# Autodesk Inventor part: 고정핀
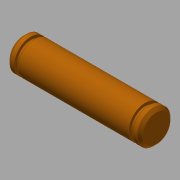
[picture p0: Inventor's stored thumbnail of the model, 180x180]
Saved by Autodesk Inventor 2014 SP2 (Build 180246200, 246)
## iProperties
Created: 2015-12
Part Number: 고정핀
Material: 스테인리스강
Document SubType Name: Modeling
Designer: mduedu
Density: 8.08 g/cm^3
Appearance: 주황색
Author: mduedu
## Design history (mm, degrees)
sketch "스케치1"
  geometry: C1 r 3 at (0, 0); 1 further point
  constraints: 1 centre point, 1 coincident
  dimensions: "d0" = 6 diameter of C1
extrude "돌출1" new body sketch "스케치1" stored distance "d1" = 24; taper "d2" = 0 deg
chamfer "모따기1" distance "d3" = 0.5; stored, may be unused: second distance "d4" = 2, angle "d5" = 45 deg
sketch "스케치2"
  geometry: L1 (-12, 2.5)-(-11.5, 3) reference; L2 (-11.5, 3)-(11.5, 3) reference; L3 (11.5, 3)-(12, 2.5) reference; L4 (12, 2.5)-(12, -2.5) reference; L5 (12, -2.5)-(11.5, -3) reference; L6 (11.5, -3)-(-11.5, -3) reference; L7 (-11.5, -3)-(-12, -2.5) reference; L8 (-12, -2.5)-(-12, 2.5) reference; L9 (10, 3)-(10.7, 3); L10 (10.7, 3)-(10.7, 2.5); L11 (10.7, 2.5)-(10, 2.5); L12 (10, 2.5)-(10, 3); L13 (0, 0)-(12, 0)
  constraints: 10 end point, 2 parallel, 1 collinear, 1 horizontal, 1 midpoint, 1 perpendicular
  dimensions: "d6" = 10 distance from line of L12 L13.start; "d7" = 5 diameter of L11 L13; "d8" = 0.7 distance of L9.start L9.end
revolve "회전1" sketch "스케치2" stored, may be unused: angle "d9" = 90 deg
node "솔리드1"
mirror "대칭1"
node "절단 모서리 투영1"
